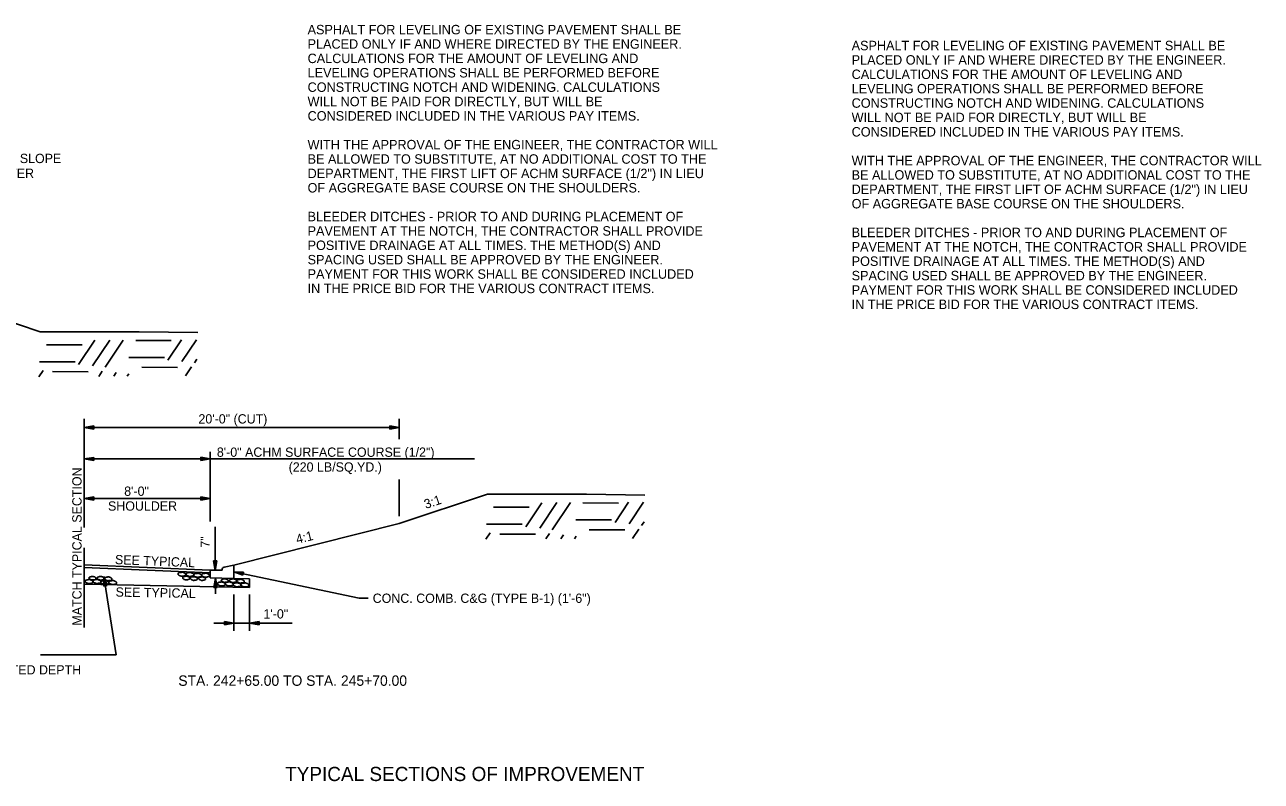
# Model space of a CAD drawing. Extents: x 1398183 to 1398373, y 1967240 to 1968889.
# Drawn here: x 1398291.7 to 1398370.2, y 1968171.2 to 1968219.2 of the extents above; entities that cross this region are included whole.
import ezdxf

# ---------------------------------------------------------------- set-up
doc = ezdxf.new("R2010")
doc.units = 0
for name, color, linetype in [('1', 7, 'Continuous'), ('10', 7, 'Continuous'), ('19', 7, 'Continuous'), ('42', 7, 'Continuous'), ('60', 7, 'Continuous'), ('9', 7, 'Continuous'), ('Level 1', 7, 'Continuous')]:
    doc.layers.add(name, color=color, linetype=linetype)

# ---------------------------------------------------------------- blocks, each defined once
blk = doc.blocks.new('ROCKS')
at = {"layer": '1'}
blk.add_spline([(0.013, 0.06), (0.053, 0.053), (0.107, 0.033), (0.133, 0.013), (0.133, -0.007), (0.12, -0.033), (0.107, -0.04), (0.073, -0.053), (0.033, -0.067), (0.013, -0.067), (-0.02, -0.06), (-0.06, -0.053), (-0.087, -0.047), (-0.113, -0.02), (-0.113, -0.007), (-0.107, 0.02), (-0.087, 0.033), (-0.067, 0.047), (-0.033, 0.053), (-0.02, 0.06), (0.013, 0.06)], degree=3, dxfattribs=at)

msp = doc.modelspace()

# ---------------------------------------------------------------- linework, layer by layer
at = {"layer": '19'}
for p, q in [((1398287.562, 1968201.39), (1398292.663, 1968199.69)), ((1398295.453, 1968187.268), (1398295.453, 1968194.165)), ((1398315.453, 1968192.882), (1398315.453, 1968194.165)), ((1398296.053, 1968193.723), (1398295.453, 1968193.618)), ((1398315.453, 1968193.618), (1398295.453, 1968193.618)), ((1398295.453, 1968193.618), (1398296.053, 1968193.513)), ((1398296.053, 1968193.668), (1398295.613, 1968193.633)), ((1398295.613, 1968193.603), (1398296.053, 1968193.563)), ((1398296.053, 1968193.513), (1398296.053, 1968193.723)), ((1398314.853, 1968193.724), (1398314.853, 1968193.514)), ((1398315.453, 1968193.618), (1398314.853, 1968193.724)), ((1398315.293, 1968193.633), (1398314.853, 1968193.669)), ((1398314.853, 1968193.514), (1398315.453, 1968193.618)), ((1398314.853, 1968193.564), (1398315.293, 1968193.603)), ((1398296.053, 1968191.723), (1398295.453, 1968191.618)), ((1398320.235, 1968191.618), (1398295.453, 1968191.618)), ((1398295.453, 1968191.618), (1398296.053, 1968191.513)), ((1398296.053, 1968191.668), (1398295.613, 1968191.633)), ((1398295.613, 1968191.603), (1398296.053, 1968191.563)), ((1398296.053, 1968191.513), (1398296.053, 1968191.723)), ((1398302.853, 1968191.724), (1398302.853, 1968191.514)), ((1398303.453, 1968191.618), (1398302.853, 1968191.724)), ((1398303.293, 1968191.633), (1398302.853, 1968191.669)), ((1398302.853, 1968191.514), (1398303.453, 1968191.618)), ((1398302.853, 1968191.564), (1398303.293, 1968191.603)), ((1398303.453, 1968187.642), (1398303.453, 1968192.08)), ((1398315.453, 1968187.98), (1398315.453, 1968190.323)), ((1398296.053, 1968189.223), (1398295.453, 1968189.118)), ((1398296.053, 1968189.168), (1398295.613, 1968189.133)), ((1398296.053, 1968189.013), (1398296.053, 1968189.223)), ((1398302.853, 1968189.224), (1398302.853, 1968189.014)), ((1398303.453, 1968189.118), (1398302.853, 1968189.224)), ((1398303.293, 1968189.134), (1398302.853, 1968189.169)), ((1398315.453, 1968187.514), (1398321.051, 1968189.38)), ((1398295.453, 1968189.118), (1398303.453, 1968189.118)), ((1398295.453, 1968189.118), (1398296.053, 1968189.013)), ((1398295.613, 1968189.103), (1398296.053, 1968189.063)), ((1398302.853, 1968189.014), (1398303.453, 1968189.118)), ((1398302.853, 1968189.064), (1398303.293, 1968189.104)), ((1398303.759, 1968187.312), (1398303.759, 1968184.548)), ((1398304.953, 1968184.889), (1398315.453, 1968187.514)), ((1398295.453, 1968180.93), (1398295.453, 1968185.981)), ((1398303.453, 1968184.071), (1398303.453, 1968184.571)), ((1398303.453, 1968184.571), (1398304.203, 1968184.556)), ((1398303.654, 1968185.148), (1398303.864, 1968185.148)), ((1398303.759, 1968184.548), (1398303.654, 1968185.148)), ((1398303.744, 1968184.708), (1398303.704, 1968185.148)), ((1398303.864, 1968185.148), (1398303.759, 1968184.548)), ((1398303.809, 1968185.148), (1398303.774, 1968184.708)), ((1398304.203, 1968184.556), (1398304.203, 1968184.589)), ((1398304.334, 1968184.752), (1398304.953, 1968184.889)), ((1398304.953, 1968184.889), (1398304.953, 1968184.041)), ((1398312.913, 1968182.781), (1398304.953, 1968184.465)), ((1398305.517, 1968184.239), (1398304.953, 1968184.465)), ((1398304.953, 1968184.465), (1398305.562, 1968184.443)), ((1398305.111, 1968184.444), (1398305.548, 1968184.392)), ((1398305.562, 1968184.443), (1398305.517, 1968184.239)), ((1398296.706, 1968184.155), (1398296.694, 1968183.546)), ((1398297.471, 1968179.187), (1398296.706, 1968184.155)), ((1398296.9, 1968183.58), (1398296.706, 1968184.155)), ((1398296.718, 1968183.996), (1398296.746, 1968183.557)), ((1398296.851, 1968183.573), (1398296.746, 1968184)), ((1398304.953, 1968184.041), (1398303.453, 1968184.071)), ((1398303.682, 1968183.464), (1398303.787, 1968184.064)), ((1398303.732, 1968183.464), (1398303.772, 1968183.904)), ((1398303.787, 1968184.064), (1398303.892, 1968183.464)), ((1398303.787, 1968184.064), (1398303.787, 1968183.064)), ((1398303.802, 1968183.904), (1398303.837, 1968183.464)), ((1398305.527, 1968184.288), (1398305.105, 1968184.416)), ((1398305.953, 1968183.473), (1398305.953, 1968184.021)), ((1398296.694, 1968183.546), (1398296.9, 1968183.58)), ((1398303.892, 1968183.464), (1398303.682, 1968183.464)), ((1398304.953, 1968183.028), (1398304.953, 1968180.706)), ((1398305.953, 1968183.028), (1398305.953, 1968180.706)), ((1398313.483, 1968182.781), (1398312.913, 1968182.781)), ((1398304.353, 1968181.303), (1398304.353, 1968181.093)), ((1398304.953, 1968181.198), (1398304.353, 1968181.303)), ((1398306.553, 1968181.303), (1398305.953, 1968181.198)), ((1398306.553, 1968181.093), (1398306.553, 1968181.303)), ((1398308.658, 1968181.198), (1398303.678, 1968181.198)), ((1398304.793, 1968181.213), (1398304.353, 1968181.248)), ((1398304.353, 1968181.093), (1398304.953, 1968181.198)), ((1398304.353, 1968181.143), (1398304.793, 1968181.183)), ((1398305.953, 1968181.198), (1398306.553, 1968181.093)), ((1398306.553, 1968181.248), (1398306.113, 1968181.213)), ((1398306.113, 1968181.183), (1398306.553, 1968181.143)), ((1398292.673, 1968179.187), (1398297.471, 1968179.187))]:
    msp.add_line(p, q, dxfattribs=at)
for points in [[(1398295.453, 1968184.891), (1398303.453, 1968184.571)], [(1398295.453, 1968184.724), (1398303.453, 1968184.404)], [(1398295.453, 1968183.683), (1398305.953, 1968183.473)], [(1398304.953, 1968184.041), (1398305.953, 1968184.021)]]:
    msp.add_lwpolyline(points, dxfattribs=at)
msp.add_lwpolyline([(1398295.453, 1968184.724), (1398303.453, 1968184.404), (1398303.453, 1968184.571), (1398295.453, 1968184.891)], close=True, dxfattribs=at)
msp.add_arc((1398304.37, 1968184.589), 0.167, 102.52881, 180, dxfattribs=at)
at = {"layer": '42'}
for points in [[(1398292.663, 1968199.69), (1398298.949, 1968199.69), (1398302.665, 1968199.64)], [(1398321.051, 1968189.38), (1398327.337, 1968189.38), (1398331.053, 1968189.33)]]:
    msp.add_lwpolyline(points, dxfattribs=at)
at = {"layer": '9'}
for p, q in [((1398295.311, 1968198.862), (1398293.049, 1968198.868)), ((1398296.118, 1968199.152), (1398295.095, 1968197.618)), ((1398297.07, 1968199.158), (1398295.985, 1968197.53)), ((1398297.93, 1968199.162), (1398296.783, 1968197.442)), ((1398300.982, 1968199.135), (1398298.72, 1968199.141)), ((1398301.628, 1968199.183), (1398300.767, 1968197.891)), ((1398302.581, 1968199.188), (1398301.657, 1968197.803)), ((1398294.872, 1968197.784), (1398292.61, 1968197.79)), ((1398300.543, 1968198.057), (1398298.282, 1968198.063)), ((1398302.609, 1968197.946), (1398302.455, 1968197.715)), ((1398292.835, 1968197.235), (1398292.571, 1968196.838)), ((1398295.709, 1968197.158), (1398293.447, 1968197.164)), ((1398296.599, 1968197.2), (1398296.372, 1968196.859)), ((1398297.49, 1968197.112), (1398297.324, 1968196.865)), ((1398298.287, 1968197.024), (1398298.184, 1968196.87)), ((1398301.381, 1968197.431), (1398299.119, 1968197.437)), ((1398302.271, 1968197.473), (1398301.883, 1968196.89)), ((1398323.699, 1968188.552), (1398321.437, 1968188.558)), ((1398324.506, 1968188.843), (1398323.483, 1968187.308)), ((1398325.458, 1968188.848), (1398324.373, 1968187.221)), ((1398326.318, 1968188.853), (1398325.171, 1968187.132)), ((1398329.37, 1968188.825), (1398327.108, 1968188.831)), ((1398330.016, 1968188.873), (1398329.155, 1968187.581)), ((1398330.969, 1968188.879), (1398330.045, 1968187.494)), ((1398328.931, 1968187.747), (1398326.669, 1968187.753)), ((1398330.997, 1968187.636), (1398330.843, 1968187.405)), ((1398321.223, 1968186.925), (1398320.959, 1968186.528)), ((1398323.26, 1968187.474), (1398320.998, 1968187.48)), ((1398324.097, 1968186.848), (1398321.835, 1968186.854)), ((1398324.987, 1968186.89), (1398324.76, 1968186.55)), ((1398325.877, 1968186.802), (1398325.712, 1968186.555)), ((1398329.769, 1968187.121), (1398327.507, 1968187.127)), ((1398330.659, 1968187.163), (1398330.271, 1968186.58)), ((1398326.675, 1968186.714), (1398326.572, 1968186.56))]:
    msp.add_line(p, q, dxfattribs=at)

# ---------------------------------------------------------------- block references
at = {"layer": 'Level 1'}
for p, xscale, yscale, rotation in [((1398301.637, 1968184.298), 2.0116542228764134, -2.011654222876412, -4.336484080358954), ((1398302.142, 1968184.287), 2.0116542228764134, -2.011654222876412, -4.336484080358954), ((1398295.782, 1968183.843), 2.0116542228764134, -2.011654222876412, 175.66351591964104), ((1398295.996, 1968184.057), 1.773922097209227, -1.7739220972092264, 175.66351591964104), ((1398296.28, 1968183.846), 2.0116542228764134, -2.011654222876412, 175.66351591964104), ((1398296.518, 1968184.049), 1.851115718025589, -1.8511157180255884, 175.66351591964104), ((1398296.774, 1968183.791), 2.0116542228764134, -2.011654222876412, 175.66351591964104), ((1398297, 1968184.019), 1.8866375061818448, -1.886637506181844, 175.66351591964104), ((1398297.279, 1968183.78), 2.0116542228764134, -2.011654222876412, 175.66351591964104), ((1398301.916, 1968184.059), 1.8866375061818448, -1.886637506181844, -4.336484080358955), ((1398302.399, 1968184.028), 1.851115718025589, -1.8511157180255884, -4.336484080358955), ((1398302.637, 1968184.232), 2.0116542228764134, -2.011654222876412, -4.336484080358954), ((1398302.92, 1968184.021), 1.773922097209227, -1.7739220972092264, -4.336484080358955), ((1398303.135, 1968184.235), 2.0116542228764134, -2.011654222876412, -4.336484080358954), ((1398304.177, 1968183.691), 2.0116542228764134, -2.011654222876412, 175.66351591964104), ((1398304.392, 1968183.905), 1.773922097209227, -1.7739220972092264, 175.66351591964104), ((1398304.675, 1968183.694), 2.0116542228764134, -2.011654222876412, 175.66351591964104), ((1398304.913, 1968183.897), 1.851115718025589, -1.8511157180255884, 175.66351591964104), ((1398305.169, 1968183.639), 2.0116542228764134, -2.011654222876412, 175.66351591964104), ((1398305.395, 1968183.867), 1.8866375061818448, -1.886637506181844, 175.66351591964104), ((1398305.674, 1968183.628), 2.0116542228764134, -2.011654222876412, 175.66351591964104)]:
    msp.add_blockref('ROCKS', p, dxfattribs=dict(at, xscale=xscale, yscale=yscale, rotation=rotation))

# ---------------------------------------------------------------- texts
at = {"layer": '10'}
for s, height, p in [('20\'-0" (CUT)', 0.59001, (1398302.703, 1968193.87)), ('8\'-0" ACHM SURFACE COURSE (1/2")', 0.59001, (1398303.873, 1968191.757)), ('(220 LB/SQ.YD.)', 0.59001, (1398308.431, 1968190.817)), ('8\'-0"', 0.59, (1398297.989, 1968189.28)), ('SHOULDER', 0.59, (1398296.962, 1968188.34)), ('1\'-0"', 0.59, (1398306.832, 1968181.493))]:
    msp.add_text(s, height=height, dxfattribs=at).set_placement(p)
for s, height, rotation, p in [('MATCH TYPICAL SECTION', 0.59001, 90, (1398295.282, 1968181.042)), ('3:1', 0.59, 18.43495, (1398317.14, 1968188.445)), ('4:1', 0.59, 14.03624, (1398308.972, 1968186.226)), ('SEE TYPICAL', 0.59001, 357.70939, (1398297.394, 1968184.948)), ('SEE TYPICAL', 0.59001, 358.98756, (1398297.438, 1968182.885))]:
    msp.add_text(s, height=height, rotation=rotation, dxfattribs=at).set_placement(p)
at = {"layer": '19'}
for s, height, p in [('ASPHALT FOR LEVELING OF EXISTING PAVEMENT SHALL BE', 0.6, (1398309.634, 1968218.568)), ('PLACED ONLY IF AND WHERE DIRECTED BY THE ENGINEER.', 0.6, (1398309.634, 1968217.656)), ('ASPHALT FOR LEVELING OF EXISTING PAVEMENT SHALL BE', 0.6, (1398344.176, 1968217.558)), ('CALCULATIONS FOR THE AMOUNT OF LEVELING AND', 0.6, (1398309.634, 1968216.743)), ('PLACED ONLY IF AND WHERE DIRECTED BY THE ENGINEER.', 0.6, (1398344.176, 1968216.646)), ('LEVELING OPERATIONS SHALL BE PERFORMED BEFORE ', 0.6, (1398309.634, 1968215.831)), ('CALCULATIONS FOR THE AMOUNT OF LEVELING AND', 0.6, (1398344.176, 1968215.733)), ('CONSTRUCTING NOTCH AND WIDENING. CALCULATIONS', 0.6, (1398309.634, 1968214.918)), ('LEVELING OPERATIONS SHALL BE PERFORMED BEFORE ', 0.6, (1398344.176, 1968214.821)), ('WILL NOT BE PAID FOR DIRECTLY, BUT WILL BE', 0.6, (1398309.634, 1968214.006)), ('CONSTRUCTING NOTCH AND WIDENING. CALCULATIONS', 0.6, (1398344.176, 1968213.908)), ('CONSIDERED INCLUDED IN THE VARIOUS PAY ITEMS.', 0.6, (1398309.634, 1968213.093)), ('WILL NOT BE PAID FOR DIRECTLY, BUT WILL BE', 0.6, (1398344.176, 1968212.996)), ('CONSIDERED INCLUDED IN THE VARIOUS PAY ITEMS.', 0.6, (1398344.176, 1968212.083)), ('WITH THE APPROVAL OF THE ENGINEER, THE CONTRACTOR WILL', 0.6, (1398309.634, 1968211.268)), ("SLOPE = 0.04'/' OR S.E. SLOPE", 0.59001, (1398282.445, 1968210.398)), ('BE ALLOWED TO SUBSTITUTE, AT NO ADDITIONAL COST TO THE', 0.6, (1398309.634, 1968210.356)), ('WITH THE APPROVAL OF THE ENGINEER, THE CONTRACTOR WILL', 0.6, (1398344.176, 1968210.258)), ('WHICHEVER IS GREATER', 0.59001, (1398282.445, 1968209.458)), ('DEPARTMENT, THE FIRST LIFT OF ACHM SURFACE (1/2") IN LIEU', 0.6, (1398309.634, 1968209.443)), ('BE ALLOWED TO SUBSTITUTE, AT NO ADDITIONAL COST TO THE', 0.6, (1398344.176, 1968209.346)), ('OF AGGREGATE BASE COURSE ON THE SHOULDERS.', 0.6, (1398309.634, 1968208.531)), ('DEPARTMENT, THE FIRST LIFT OF ACHM SURFACE (1/2") IN LIEU', 0.6, (1398344.176, 1968208.433)), ('OF AGGREGATE BASE COURSE ON THE SHOULDERS.', 0.6, (1398344.176, 1968207.521)), ('BLEEDER DITCHES - PRIOR TO AND DURING PLACEMENT OF', 0.6, (1398309.634, 1968206.706)), ('PAVEMENT AT THE NOTCH, THE CONTRACTOR SHALL PROVIDE', 0.6, (1398309.634, 1968205.793)), ('BLEEDER DITCHES - PRIOR TO AND DURING PLACEMENT OF', 0.6, (1398344.176, 1968205.696)), ('POSITIVE DRAINAGE AT ALL TIMES. THE METHOD(S) AND', 0.6, (1398309.634, 1968204.881)), ('PAVEMENT AT THE NOTCH, THE CONTRACTOR SHALL PROVIDE', 0.6, (1398344.176, 1968204.783)), ('SPACING USED SHALL BE APPROVED BY THE ENGINEER.', 0.6, (1398309.634, 1968203.968)), ('POSITIVE DRAINAGE AT ALL TIMES. THE METHOD(S) AND', 0.6, (1398344.176, 1968203.871)), ('PAYMENT FOR THIS WORK SHALL BE CONSIDERED INCLUDED', 0.6, (1398309.634, 1968203.056)), ('SPACING USED SHALL BE APPROVED BY THE ENGINEER.', 0.6, (1398344.176, 1968202.958)), ('IN THE PRICE BID FOR THE VARIOUS CONTRACT ITEMS.', 0.6, (1398309.634, 1968202.143)), ('PAYMENT FOR THIS WORK SHALL BE CONSIDERED INCLUDED', 0.6, (1398344.176, 1968202.046)), ('IN THE PRICE BID FOR THE VARIOUS CONTRACT ITEMS.', 0.6, (1398344.176, 1968201.133)), ('CONC. COMB. C&G (TYPE B-1) (1\'-6")', 0.59001, (1398313.768, 1968182.486)), ('STA. 242+65.00 TO STA. 245+70.00 ', 0.65999, (1398301.425, 1968177.223))]:
    msp.add_text(s, height=height, dxfattribs=at).set_placement(p)
msp.add_text('(CLASS 7) - VAR. COMPACTED DEPTH', height=0.59001, rotation=360, dxfattribs=at).set_placement((1398280.788, 1968177.943))
at = {"layer": '42'}
msp.add_text('7"', height=0.59, rotation=90, dxfattribs=at).set_placement((1398303.425, 1968185.992))
at = {"layer": '60'}
msp.add_text('TYPICAL SECTIONS OF IMPROVEMENT', height=0.9, dxfattribs=at).set_placement((1398308.207, 1968171.179))

doc.saveas('drawing.dxf')
